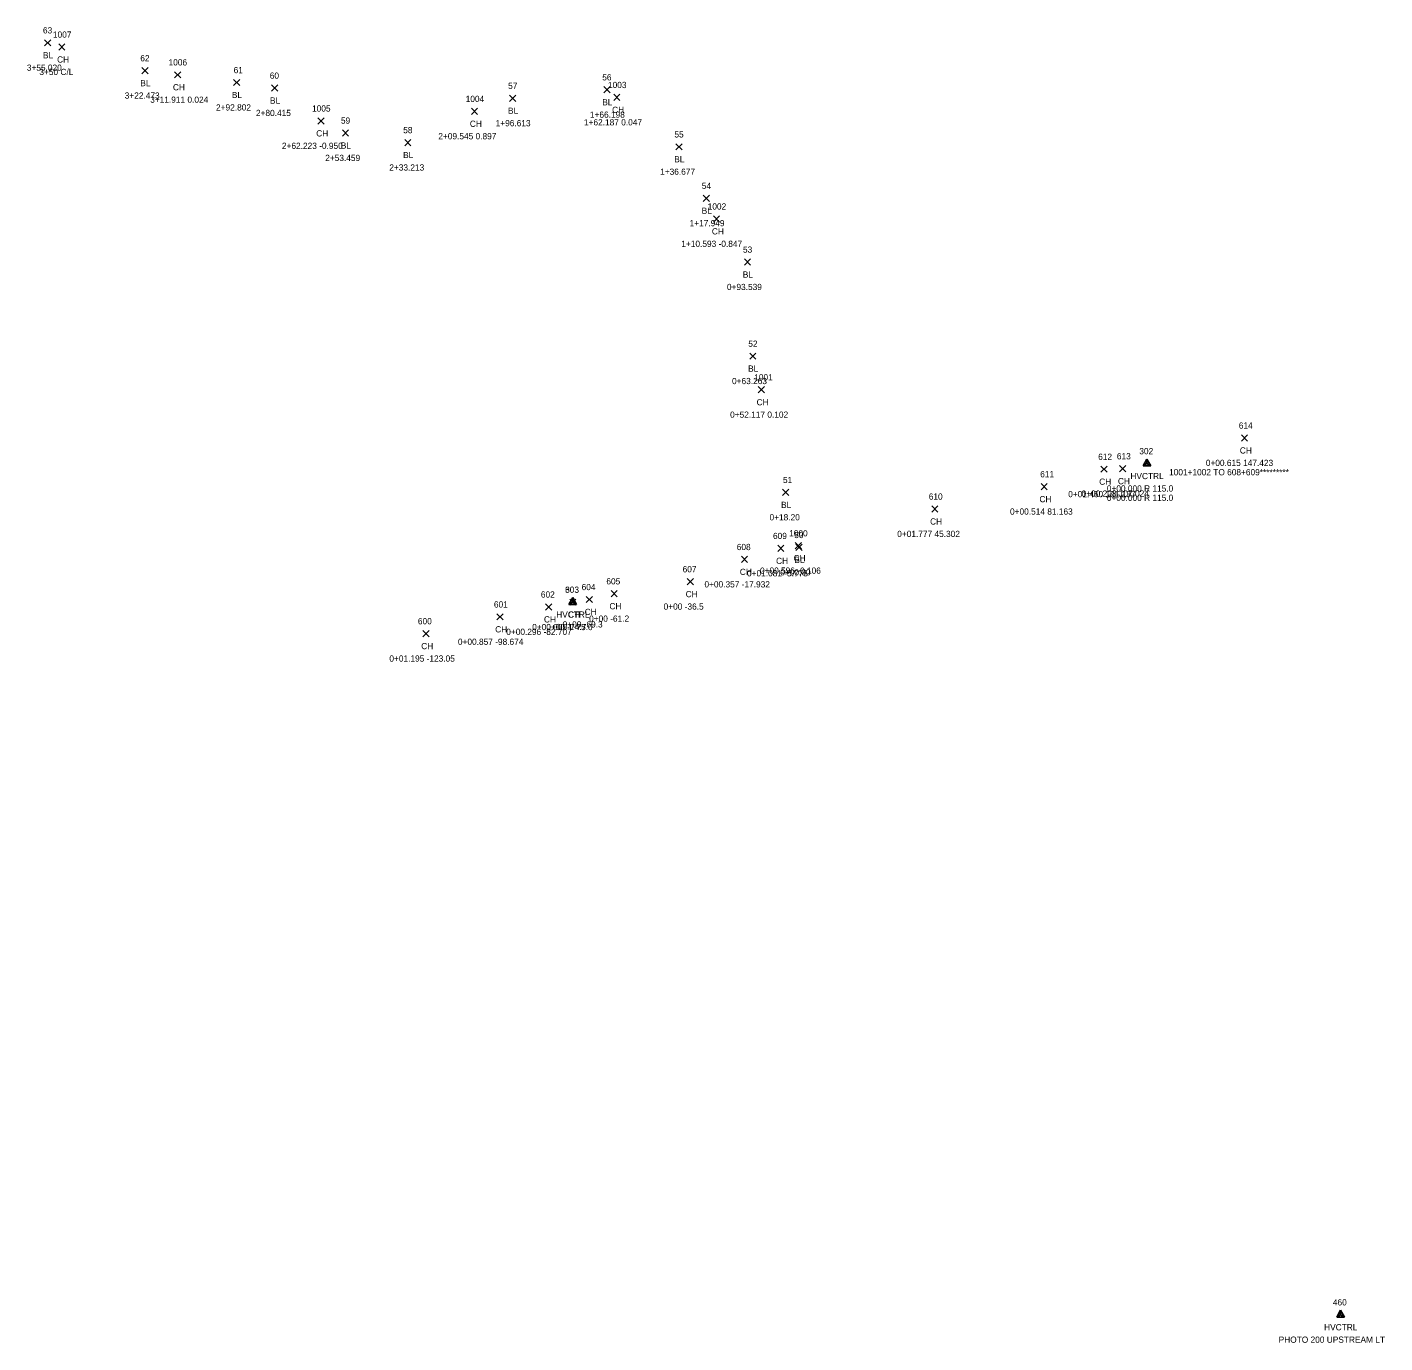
# Model space of a CAD drawing. Extents: x 89316 to 92454, y 84175 to 86051.
# Drawn here: x 91573.5 to 92009.8, y 84174.8 to 84597.7 of the extents above; entities that cross this region are included whole.
import ezdxf

# ---------------------------------------------------------------- set-up
doc = ezdxf.new("R2010")
doc.units = 0
for name, color, linetype in [('C_A', 7, 'Continuous'), ('C_C', 7, 'Continuous'), ('C_I', 7, 'Continuous'), ('C_TIC', 7, 'Continuous'), ('CPSM', 7, 'Continuous'), ('L_A', 7, 'Continuous'), ('L_C', 7, 'Continuous'), ('L_I', 7, 'Continuous'), ('L_TIC', 7, 'Continuous')]:
    doc.layers.add(name, color=color, linetype=linetype)

msp = doc.modelspace()

# ---------------------------------------------------------------- linework, layer by layer
at = {"layer": 'C_TIC'}
for points in [[(91579.07, 84591.69), (91581.07, 84593.69)], [(91581.07, 84591.69), (91579.07, 84593.69)], [(91610.36, 84582.73), (91612.36, 84584.73)], [(91612.36, 84582.73), (91610.36, 84584.73)], [(91639.79, 84578.92), (91641.79, 84580.92)], [(91641.79, 84578.92), (91639.79, 84580.92)], [(91652.04, 84577.14), (91654.04, 84579.14)], [(91654.04, 84577.14), (91652.04, 84579.14)], [(91758.82, 84576.59), (91760.82, 84578.59)], [(91760.82, 84576.59), (91758.82, 84578.59)], [(91728.52, 84573.86), (91730.52, 84575.86)], [(91730.52, 84573.86), (91728.52, 84575.86)], [(91674.79, 84562.68), (91676.79, 84564.68)], [(91676.79, 84562.68), (91674.79, 84564.68)], [(91694.81, 84559.62), (91696.81, 84561.62)], [(91696.81, 84559.62), (91694.81, 84561.62)], [(91781.95, 84558.25), (91783.95, 84560.25)], [(91783.95, 84558.25), (91781.95, 84560.25)], [(91790.76, 84541.72), (91792.76, 84543.72)], [(91792.76, 84541.72), (91790.76, 84543.72)], [(91803.98, 84521.2), (91805.98, 84523.2)], [(91805.98, 84521.2), (91803.98, 84523.2)], [(91805.7, 84490.97), (91807.7, 84492.97)], [(91807.7, 84490.97), (91805.7, 84492.97)], [(91816.27, 84447.17), (91818.27, 84449.17)], [(91818.27, 84447.17), (91816.27, 84449.17)], [(91820.54, 84429.48), (91822.54, 84431.48)], [(91822.54, 84429.48), (91820.54, 84431.48)]]:
    msp.add_lwpolyline(points, dxfattribs=at)
at = {"layer": 'CPSM'}
for p, q in [((91932.09, 84456.71), (91933.34, 84458.88)), ((91932.09, 84456.71), (91933.34, 84457.43)), ((91932.09, 84456.71), (91934.59, 84456.71)), ((91934.59, 84456.71), (91933.34, 84458.88)), ((91933.34, 84457.43), (91933.34, 84458.88)), ((91933.34, 84457.43), (91933.34, 84457.43)), ((91933.34, 84457.43), (91934.59, 84456.71)), ((91747.56, 84412.17), (91748.81, 84414.34)), ((91747.56, 84412.17), (91748.81, 84412.89)), ((91747.56, 84412.17), (91750.06, 84412.17)), ((91750.06, 84412.17), (91748.81, 84414.34)), ((91748.81, 84412.89), (91748.81, 84414.34)), ((91748.81, 84412.89), (91748.81, 84412.89)), ((91748.81, 84412.89), (91750.06, 84412.17)), ((91994.33, 84183.11), (91995.58, 84185.28)), ((91996.83, 84183.11), (91995.58, 84185.28)), ((91995.58, 84183.83), (91995.58, 84185.28)), ((91994.33, 84183.11), (91995.58, 84183.83)), ((91994.33, 84183.11), (91996.83, 84183.11)), ((91995.58, 84183.83), (91995.58, 84183.83)), ((91995.58, 84183.83), (91996.83, 84183.11))]:
    msp.add_line(p, q, dxfattribs=at)
at = {"layer": 'L_TIC'}
for points in [[(91583.62, 84590.32), (91585.62, 84592.32)], [(91585.62, 84590.32), (91583.62, 84592.32)], [(91620.84, 84581.4), (91622.84, 84583.4)], [(91622.84, 84581.4), (91620.84, 84583.4)], [(91761.99, 84574.13), (91763.99, 84576.13)], [(91763.99, 84574.13), (91761.99, 84576.13)], [(91716.26, 84569.66), (91718.26, 84571.66)], [(91718.26, 84569.66), (91716.26, 84571.66)], [(91666.89, 84566.58), (91668.89, 84568.58)], [(91668.89, 84566.58), (91666.89, 84568.58)], [(91794.03, 84535.08), (91796.03, 84537.08)], [(91796.03, 84535.08), (91794.03, 84537.08)], [(91808.41, 84480.16), (91810.41, 84482.16)], [(91810.41, 84480.16), (91808.41, 84482.16)], [(91963.7, 84464.66), (91965.7, 84466.66)], [(91965.7, 84464.66), (91963.7, 84466.66)], [(91918.51, 84454.62), (91920.51, 84456.62)], [(91920.51, 84454.62), (91918.51, 84456.62)], [(91924.52, 84454.79), (91926.52, 84456.79)], [(91926.52, 84454.79), (91924.52, 84456.79)], [(91899.31, 84449.02), (91901.31, 84451.02)], [(91901.31, 84449.02), (91899.31, 84451.02)], [(91864.16, 84441.83), (91866.16, 84443.83)], [(91866.16, 84441.83), (91864.16, 84443.83)], [(91814.67, 84429.17), (91816.67, 84431.17)], [(91816.67, 84429.17), (91814.67, 84431.17)], [(91820.29, 84430.03), (91822.29, 84432.03)], [(91822.29, 84430.03), (91820.29, 84432.03)], [(91803.02, 84425.62), (91805.02, 84427.62)], [(91805.02, 84425.62), (91803.02, 84427.62)], [(91761.11, 84414.59), (91763.11, 84416.59)], [(91763.11, 84414.59), (91761.11, 84416.59)], [(91785.62, 84418.48), (91787.62, 84420.48)], [(91787.62, 84418.48), (91785.62, 84420.48)], [(91740.07, 84410.36), (91742.07, 84412.36)], [(91742.07, 84410.36), (91740.07, 84412.36)], [(91747.86, 84411.9), (91749.86, 84413.9)], [(91749.86, 84411.9), (91747.86, 84413.9)], [(91753.16, 84412.75), (91755.16, 84414.75)], [(91755.16, 84412.75), (91753.16, 84414.75)], [(91724.42, 84407.16), (91726.42, 84409.16)], [(91726.42, 84407.16), (91724.42, 84409.16)], [(91700.64, 84401.77), (91702.64, 84403.77)], [(91702.64, 84401.77), (91700.64, 84403.77)]]:
    msp.add_lwpolyline(points, dxfattribs=at)

# ---------------------------------------------------------------- texts
at = {"layer": 'C_A'}
for s, p in [('BL', (91578.56, 84587.69)), ('BL', (91609.85, 84578.73)), ('BL', (91639.27, 84574.92)), ('BL', (91651.53, 84573.14)), ('BL', (91758.3, 84572.59)), ('BL', (91728.01, 84569.86)), ('BL', (91674.28, 84558.68)), ('BL', (91694.3, 84555.62)), ('BL', (91781.44, 84554.25)), ('BL', (91790.25, 84537.72)), ('BL', (91803.47, 84517.2)), ('BL', (91805.18, 84486.97)), ('HVCTRL', (91928.03, 84452.43)), ('BL', (91815.76, 84443.17)), ('BL', (91820.03, 84425.48)), ('HVCTRL', (91743.5, 84407.89)), ('HVCTRL', (91990.28, 84178.83))]:
    msp.add_text(s, height=2, dxfattribs=at).set_placement(p)
at = {"layer": 'C_C'}
for s, p in [('3+55.020', (91573.38, 84583.69)), ('3+22.473', (91604.84, 84574.73)), ('2+92.802', (91634.19, 84570.92)), ('2+80.415', (91647.01, 84569.14)), ('1+66.198', (91754.33, 84568.59)), ('1+96.613', (91724.04, 84565.86)), ('2+53.459', (91669.27, 84554.68)), ('2+33.213', (91689.86, 84551.62)), ('1+36.677', (91776.9, 84550.25)), ('1+17.949', (91786.37, 84533.72)), ('0+93.539', (91798.37, 84513.2)), ('0+63.263', (91800, 84482.97)), ('0+00.000 R 115.0', (91920.45, 84448.43)), ('0+00.000 R 115.0', (91920.45, 84445.43)), ('0+18.20', (91812.05, 84439.17)), ('0+00.00', (91815.51, 84421.48)), ('0+00.000 L 75.0', (91735.78, 84403.89)), ('PHOTO 200 UPSTREAM LT', (91975.67, 84174.83))]:
    msp.add_text(s, height=2, dxfattribs=at).set_placement(p)
at = {"layer": 'C_I'}
for s, p in [('63', (91578.56, 84595.69)), ('62', (91609.85, 84586.73)), ('61', (91639.84, 84582.92)), ('60', (91651.45, 84581.14)), ('56', (91758.3, 84580.59)), ('57', (91728.06, 84577.86)), ('59', (91674.32, 84566.68)), ('58', (91694.34, 84563.62)), ('55', (91781.48, 84562.25)), ('54', (91790.3, 84545.72)), ('53', (91803.52, 84525.2)), ('52', (91805.23, 84494.97)), ('302', (91930.89, 84460.43)), ('51', (91816.37, 84451.17)), ('50', (91819.99, 84433.48)), ('303', (91746.37, 84415.89)), ('460', (91993.09, 84186.83))]:
    msp.add_text(s, height=2, dxfattribs=at).set_placement(p)
at = {"layer": 'L_A'}
for p in [(91583.11, 84586.32), (91620.33, 84577.4), (91761.48, 84570.13), (91715.75, 84565.66), (91666.38, 84562.58), (91793.52, 84531.08), (91807.9, 84476.16), (91963.19, 84460.66), (91918, 84450.62), (91924.01, 84450.79), (91898.8, 84445.02), (91863.65, 84437.83), (91814.16, 84425.17), (91819.78, 84426.03), (91802.51, 84421.62), (91785.11, 84414.48), (91760.6, 84410.59), (91739.56, 84406.36), (91747.35, 84407.9), (91752.65, 84408.75), (91723.9, 84403.16), (91700.12, 84397.77)]:
    msp.add_text('CH', height=2, dxfattribs=at).set_placement(p)
at = {"layer": 'L_C'}
for s, p in [('3+50 C/L', (91577.41, 84582.32)), ('3+11.911 0.024', (91613.02, 84573.4)), ('1+62.187 0.047', (91752.42, 84566.13)), ('2+62.223 -0.950', (91655.36, 84558.58)), ('2+09.545 0.897', (91705.61, 84561.66)), ('1+10.593 -0.847', (91783.7, 84527.08)), ('0+52.117 0.102', (91799.38, 84472.16)), ('1001+1002 TO 608+609*********', (91940.45, 84453.66)), ('0+00.615 147.423', (91952.26, 84456.66)), ('0+01.460 101.137', (91908.04, 84446.62)), ('0+00.208 107.024', (91912.33, 84446.79)), ('0+00.514 81.163', (91889.34, 84441.02)), ('0+01.777 45.302', (91853.09, 84433.83)), ('0+01.081 -5.775', (91804.82, 84421.17)), ('0+00.596 -0.106', (91809, 84422.03)), ('0+00.357 -17.932', (91791.14, 84417.62)), ('0+00 -36.5', (91778.02, 84410.48)), ('0+00 -61.2', (91754.08, 84406.59)), ('0+00.296 -82.707', (91727.45, 84402.36)), ('0+00 -74.7', (91740.31, 84403.9)), ('0+00 -69.3', (91745.56, 84404.75)), ('0+00.857 -98.674', (91711.92, 84399.16)), ('0+01.195 -123.05', (91689.89, 84393.77))]:
    msp.add_text(s, height=2, dxfattribs=at).set_placement(p)
at = {"layer": 'L_I'}
for s, p in [('1007', (91581.77, 84594.32)), ('1006', (91618.93, 84585.4)), ('1003', (91760.14, 84578.13)), ('1004', (91714.41, 84573.66)), ('1005', (91665.04, 84570.58)), ('1002', (91792.18, 84539.08)), ('1001', (91807.13, 84484.16)), ('614', (91962.86, 84468.66)), ('612', (91917.67, 84458.62)), ('613', (91923.68, 84458.79)), ('611', (91899.04, 84453.02)), ('610', (91863.23, 84445.83)), ('609', (91813.17, 84433.17)), ('1000', (91818.36, 84434.03)), ('608', (91801.53, 84429.62)), ('607', (91784.13, 84422.48)), ('602', (91738.58, 84414.36)), ('603', (91746.37, 84415.9)), ('604', (91751.67, 84416.75)), ('605', (91759.62, 84418.59)), ('601', (91723.49, 84411.16)), ('600', (91699.06, 84405.77))]:
    msp.add_text(s, height=2, dxfattribs=at).set_placement(p)

doc.saveas('drawing.dxf')
